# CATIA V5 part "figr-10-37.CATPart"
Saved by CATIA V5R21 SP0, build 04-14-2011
Part number: Part1
Bounding box of the stored display mesh (mm): x -322.306 to 0, y -118.205 to 88.531, z 0 to 101.949
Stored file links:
  D:\CATIA V5R21 E-RESOURCES\CATIA-V5R21\catia-v5r21-prt\c10-catia-v5r20-prt\c10-catia-v5r21-figr-10-37.CATPart
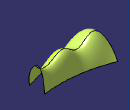
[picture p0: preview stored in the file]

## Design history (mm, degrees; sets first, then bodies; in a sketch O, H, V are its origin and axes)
Set1
  Curve1: Elements (vertex of Sketch2; vertex of Sketch1; vertex of Sketch3)
  Loft1: Sections (Sketch4; Curve1), Guides (Sketch2; Sketch1; Sketch3)
Body1 (main body)
  Sketch1 on zx-plane, origin (0, 0, 0), H (-1, 0, 0), V (0, 0, 1)
    spline S1 through (0, 96.336) (70.1946, 72.4244) (144.1119, 96.336) (203.5098, 63.985) (253.668, 92.1163) (322.3056, 72.4244)
    point P1 (0, 96.336)
    coincidence: P1 V
  Sketch2 on xy-plane, origin (0, 0, 0), H (1, 0, 0), V (0, 1, 0)
    point P1 (0, 47.0553)
    arc A1 centre (-78.7604, 671.3501) radius 629.2433 from (0, 47.0553) to (-315.9706, 88.5306) cw
    coincidence: P1 V
  Sketch3 on xy-plane, origin (0, 0, 0), H (1, 0, 0), V (0, 1, 0)
    line L1 (0, -26.5991) -> (-311.8959, -118.2048)
    point P1 (0, -26.5991)
    coincidence: P1 V
  Sketch4 on yz-plane, origin (0, 0, 0), H (0, 1, 0), V (0, 0, 1)
    point P1 (-26.5991, 0)
    point P2 (0, 58.544)
    point P3 (47.0553, 0)
    reference projected point E1 (47.0553, 0) from vertex of Sketch2
    reference projected point E2 (-26.5991, 0) from vertex of Sketch3
    spline S1 through (-26.5991, 0) (-29.9268, 35.6209) (0, 96.336) (47.0553, 0)
    reference projected point E3 (0, 96.336) from vertex of Sketch1
    point P4 (-26.5991, 0)
    point P5 (0, 96.336)
    point P6 (47.0553, 0)
    coincidence: P1 H, P3 H, E1 P3, P1 E2, P4 P1, P5 V, P6 P3, E3 S1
